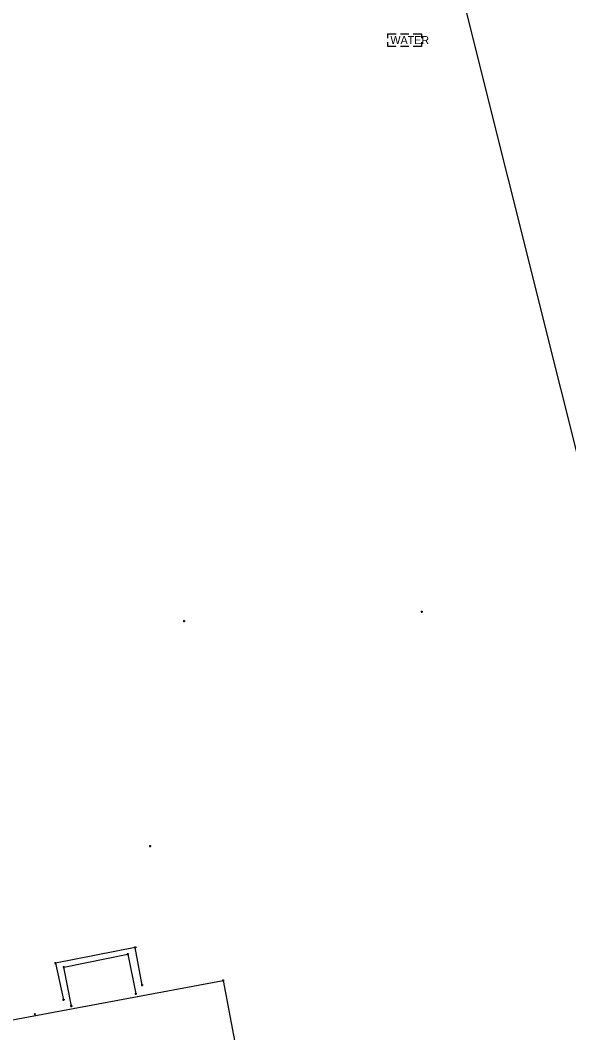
# Model space of a CAD drawing. Extents: x 1954856 to 2011933, y 399149 to 426294.
# Drawn here: x 2005370.7 to 2005435.7, y 405566.8 to 405686.9 of the extents above; entities that cross this region are included whole.
import ezdxf

# ---------------------------------------------------------------- set-up
doc = ezdxf.new("R2010")
doc.units = 0
for name, color, linetype in [('Building_ep', 7, 'Continuous'), ('BuildingOH_ep', 7, 'Continuous'), ('ConcSlabs_ep', 7, 'Continuous'), ('FFElev_ep', 7, 'Continuous'), ('MeterWater_ep', 7, 'Continuous'), ('PointLocator_ep', 7, 'Continuous'), ('TreeLineScatter_ep', 7, 'Continuous')]:
    doc.layers.add(name, color=color, linetype=linetype)

msp = doc.modelspace()

# ---------------------------------------------------------------- linework, layer by layer
at = {"layer": 'Building_ep'}
msp.add_lwpolyline([(2005399.22, 405549.3), (2005348.21, 405539.68), (2005347.84, 405541.65), (2005337.81, 405539.76), (2005334.07, 405559.61), (2005344, 405561.48), (2005343.63, 405563.44), (2005394.75, 405572.97)], close=True, dxfattribs=at)
at = {"layer": 'BuildingOH_ep'}
msp.add_lwpolyline([(2005385.13, 405572.41), (2005384.32, 405576.88), (2005374.86, 405575.02), (2005375.81, 405570.65)], dxfattribs=at)
at = {"layer": 'ConcSlabs_ep'}
msp.add_lwpolyline([(2005376.74, 405569.92), (2005375.83, 405574.55), (2005383.45, 405576.08), (2005384.39, 405571.39)], dxfattribs=at)
at = {"layer": 'FFElev_ep'}
for p, q in [((2005372.49, 405568.87), (2005372.32, 405569.05)), ((2005372.49, 405569.05), (2005372.32, 405568.87)), ((2005372.41, 405568.96), (2005372.41, 405568.96))]:
    msp.add_line(p, q, dxfattribs=at)
at = {"layer": 'MeterWater_ep'}
msp.add_line((2005416.28, 405684.58), (2005416.28, 405684.58), dxfattribs=at)
for points in [[(2005414.28, 405684.83), (2005414.28, 405685.33), (2005415.28, 405685.33)], [(2005415.78, 405685.33), (2005416.78, 405685.33)], [(2005417.28, 405685.33), (2005418.28, 405685.33), (2005418.28, 405684.83)], [(2005415.28, 405683.83), (2005414.28, 405683.83), (2005414.28, 405684.33)], [(2005416.78, 405683.83), (2005415.78, 405683.83)], [(2005418.28, 405684.33), (2005418.28, 405683.83), (2005417.28, 405683.83)]]:
    msp.add_lwpolyline(points, dxfattribs=at)
at = {"layer": 'PointLocator_ep'}
for p, q in [((2005418.45, 405616.7), (2005418.2, 405616.7)), ((2005418.32, 405616.58), (2005418.32, 405616.83)), ((2005418.32, 405616.7), (2005418.32, 405616.7)), ((2005390.23, 405615.6), (2005389.98, 405615.6)), ((2005390.11, 405615.48), (2005390.11, 405615.73)), ((2005390.11, 405615.6), (2005390.11, 405615.6)), ((2005386.21, 405588.89), (2005385.96, 405588.89)), ((2005386.09, 405588.77), (2005386.09, 405589.02)), ((2005386.09, 405588.89), (2005386.09, 405588.89)), ((2005383.45, 405575.95), (2005383.45, 405576.2)), ((2005384.45, 405576.88), (2005384.2, 405576.88)), ((2005384.32, 405576.75), (2005384.32, 405577)), ((2005384.32, 405576.88), (2005384.32, 405576.88)), ((2005374.98, 405575.02), (2005374.73, 405575.02)), ((2005374.86, 405574.9), (2005374.86, 405575.15)), ((2005374.86, 405575.02), (2005374.86, 405575.02)), ((2005383.57, 405576.08), (2005383.32, 405576.08)), ((2005383.45, 405576.08), (2005383.45, 405576.08)), ((2005375.96, 405574.55), (2005375.71, 405574.55)), ((2005375.83, 405574.42), (2005375.83, 405574.67)), ((2005375.83, 405574.55), (2005375.83, 405574.55)), ((2005394.88, 405572.97), (2005394.62, 405572.97)), ((2005394.75, 405572.84), (2005394.75, 405573.09)), ((2005394.75, 405572.97), (2005394.75, 405572.97)), ((2005384.51, 405571.39), (2005384.26, 405571.39)), ((2005384.39, 405571.27), (2005384.39, 405571.52)), ((2005384.39, 405571.39), (2005384.39, 405571.39)), ((2005385.26, 405572.41), (2005385.01, 405572.41)), ((2005385.13, 405572.29), (2005385.13, 405572.54)), ((2005385.13, 405572.41), (2005385.13, 405572.41)), ((2005375.94, 405570.65), (2005375.69, 405570.65)), ((2005375.81, 405570.53), (2005375.81, 405570.78)), ((2005375.81, 405570.65), (2005375.81, 405570.65)), ((2005376.86, 405569.92), (2005376.61, 405569.92)), ((2005376.74, 405569.8), (2005376.74, 405570.05)), ((2005376.74, 405569.92), (2005376.74, 405569.92))]:
    msp.add_line(p, q, dxfattribs=at)
at = {"layer": 'TreeLineScatter_ep'}
msp.add_lwpolyline([(2005459.85, 405543.21), (2005422.31, 405693.21), (2005304.82, 405701.31)], dxfattribs=at)

# ---------------------------------------------------------------- texts
at = {"layer": 'MeterWater_ep'}
msp.add_text('WATER', height=0.95, dxfattribs=at).set_placement((2005414.59, 405684.11))

doc.saveas('drawing.dxf')
